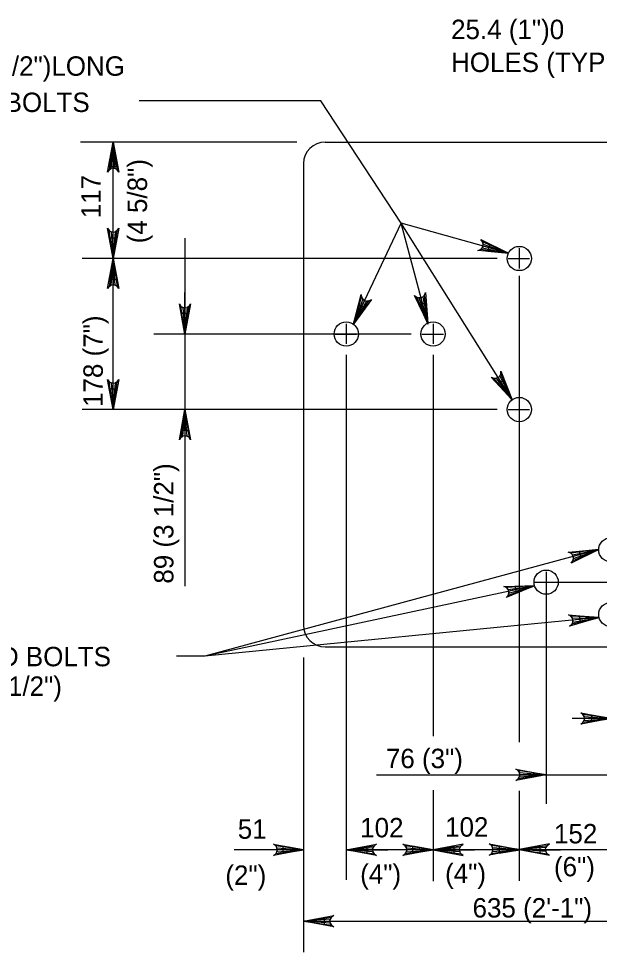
# Model space of a CAD drawing. Extents: x 0 to 36.3, y -66 to 0.
# Drawn here: x 13.18 to 16.77, y -15.09 to -9.32 of the extents above; entities that cross this region are included whole.
import ezdxf

# ---------------------------------------------------------------- set-up
doc = ezdxf.new("R2010")
doc.units = 0
doc.layers.add('2', color=7, linetype='Continuous')
doc.layers.add('3', color=7, linetype='Continuous')

msp = doc.modelspace()

# ---------------------------------------------------------------- linework, layer by layer
at = {"layer": '2'}
for p, q in [((15.0717, -10.0812), (18.1016, -10.0812)), ((14.9385, -10.2145), (14.9385, -13.0677)), ((16.2722, -10.7371), (16.2722, -10.862)), ((16.2028, -10.8009), (16.3361, -10.8009)), ((15.2025, -11.2038), (15.2025, -11.3287)), ((15.7394, -11.2038), (15.7394, -11.3287)), ((15.1331, -11.2677), (15.2663, -11.2677)), ((15.67, -11.2677), (15.8033, -11.2677)), ((16.2722, -11.6706), (16.2722, -11.7954)), ((16.2028, -11.7344), (16.3361, -11.7344)), ((16.4384, -12.7372), (16.4384, -12.862)), ((16.3691, -12.801), (16.5023, -12.801))]:
    msp.add_line(p, q, dxfattribs=at)
for centre in [(16.2722, -10.801), (15.2025, -11.2677), (15.7394, -11.2677), (16.2722, -11.7344), (16.8385, -12.601), (16.4385, -12.801), (16.8385, -13.001)]:
    msp.add_circle(centre, 0.075, dxfattribs=at)
for centre, start, end in [((15.0718, -10.2145), 90, 180), ((15.0718, -13.0677), 180, 270)]:
    msp.add_arc(centre, 0.1333, start, end, dxfattribs=at)
at = {"layer": '3'}
for p, q in [((15.0462, -9.8263), (13.9212, -9.8263)), ((15.543, -10.5827), (15.0462, -9.8263)), ((14.5169, -10.0812), (13.5602, -10.0812)), ((13.7607, -10.8009), (13.7607, -10.0812)), ((14.8968, -10.0812), (14.5169, -10.0812)), ((15.2467, -11.207), (15.543, -10.5827)), ((15.7061, -11.2005), (15.543, -10.5827)), ((16.2282, -11.6736), (15.543, -10.5827)), ((16.2048, -10.7682), (15.543, -10.5827)), ((14.2055, -10.6744), (14.2055, -12.8257)), ((14.4444, -10.8009), (13.5687, -10.8009)), ((13.7607, -11.7344), (13.7607, -10.8009)), ((16.1362, -10.8009), (14.4336, -10.8009)), ((16.2722, -10.9074), (16.2722, -13.789)), ((14.2055, -11.2677), (14.2055, -11.0116)), ((15.6033, -11.2677), (14.0134, -11.2677)), ((15.2025, -11.3954), (15.2025, -14.6398)), ((15.7394, -11.3954), (15.7394, -13.7531)), ((14.2707, -11.7344), (13.5687, -11.7344)), ((14.6835, -11.7344), (14.0134, -11.7344)), ((16.1362, -11.7344), (14.4336, -11.7344)), ((14.2055, -11.8624), (14.2055, -11.8277)), ((16.7634, -12.6002), (14.3277, -13.2589)), ((16.5009, -12.801), (18.7591, -12.801)), ((16.3668, -12.8232), (14.3277, -13.2589)), ((16.4384, -12.8635), (16.4384, -14.1707)), ((16.7658, -13.0195), (14.3277, -13.2589)), ((15.0717, -13.201), (18.1016, -13.201)), ((14.3277, -13.2589), (14.1525, -13.2589)), ((14.9385, -13.2664), (14.9385, -14.6467)), ((16.7184, -13.6429), (16.5984, -13.6429)), ((15.3898, -13.9908), (17.0763, -13.9908)), ((15.7394, -14.0854), (15.7394, -14.6492)), ((16.2722, -14.0899), (16.2722, -14.6467)), ((14.9385, -14.3606), (14.9385, -15.0885)), ((14.9385, -14.4546), (14.5105, -14.4546)), ((14.8104, -14.4546), (14.6823, -14.4546)), ((15.4833, -14.4546), (15.2349, -14.4546)), ((15.3306, -14.4546), (15.4587, -14.4546)), ((15.6114, -14.4546), (15.4833, -14.4546)), ((16.0203, -14.4546), (15.7718, -14.4546)), ((15.8675, -14.4546), (15.9956, -14.4546)), ((16.1483, -14.4546), (16.0203, -14.4546)), ((16.4003, -14.4546), (16.5283, -14.4546)), ((16.9437, -14.4546), (16.4003, -14.4546)), ((14.9385, -14.8964), (18.2348, -14.8964))]:
    msp.add_line(p, q, dxfattribs=at)
for points in [[(13.7607, -10.0812), (13.7957, -10.2676), (13.7858, -10.2532), (13.7732, -10.2458), (13.7607, -10.2437), (13.7482, -10.2458), (13.7357, -10.2532), (13.7258, -10.2676), (13.7607, -10.0812), (13.7357, -10.2532), (13.7482, -10.2458), (13.7607, -10.0812), (13.7607, -10.2437), (13.7732, -10.2458), (13.7607, -10.0812), (13.7858, -10.2532)], [(13.7607, -10.8009), (13.7258, -10.6145), (13.7357, -10.6288), (13.7482, -10.6363), (13.7607, -10.6384), (13.7732, -10.6363), (13.7858, -10.6288), (13.7957, -10.6145), (13.7607, -10.8009), (13.7858, -10.6288), (13.7732, -10.6363), (13.7607, -10.8009), (13.7607, -10.6384), (13.7482, -10.6363), (13.7607, -10.8009), (13.7357, -10.6288)], [(16.2048, -10.7682), (16.0158, -10.7515), (16.0323, -10.7458), (16.0428, -10.7357), (16.0482, -10.7243), (16.0496, -10.7118), (16.0458, -10.6977), (16.0347, -10.6843), (16.2048, -10.7682), (16.0458, -10.6977), (16.0496, -10.7118), (16.2048, -10.7682), (16.0482, -10.7243), (16.0428, -10.7357), (16.2048, -10.7682), (16.0323, -10.7458)], [(13.7607, -10.8009), (13.7957, -10.9873), (13.7858, -10.973), (13.7732, -10.9656), (13.7607, -10.9634), (13.7482, -10.9656), (13.7357, -10.973), (13.7258, -10.9873), (13.7607, -10.8009), (13.7357, -10.973), (13.7482, -10.9656), (13.7607, -10.8009), (13.7607, -10.9634), (13.7732, -10.9656), (13.7607, -10.8009), (13.7858, -10.973)], [(15.7061, -11.2005), (15.6247, -11.0292), (15.638, -11.0405), (15.652, -11.0445), (15.6646, -11.0434), (15.6762, -11.0381), (15.6863, -11.0277), (15.6923, -11.0113), (15.7061, -11.2005), (15.6863, -11.0277), (15.6762, -11.0381), (15.7061, -11.2005), (15.6646, -11.0434), (15.652, -11.0445), (15.7061, -11.2005), (15.638, -11.0405)], [(15.2467, -11.207), (15.295, -11.0236), (15.2978, -11.0408), (15.306, -11.0529), (15.3163, -11.0602), (15.3286, -11.0636), (15.343, -11.0623), (15.3582, -11.0536), (15.2467, -11.207), (15.343, -11.0623), (15.3286, -11.0636), (15.2467, -11.207), (15.3163, -11.0602), (15.306, -11.0529), (15.2467, -11.207), (15.2978, -11.0408)], [(14.2055, -11.2677), (14.1706, -11.0812), (14.1805, -11.0956), (14.193, -11.103), (14.2055, -11.1052), (14.218, -11.103), (14.2305, -11.0956), (14.2404, -11.0812), (14.2055, -11.2677), (14.2305, -11.0956), (14.218, -11.103), (14.2055, -11.2677), (14.2055, -11.1052), (14.193, -11.103), (14.2055, -11.2677), (14.1805, -11.0956)], [(16.2282, -11.6736), (16.0995, -11.5343), (16.1156, -11.5412), (16.1301, -11.5408), (16.1418, -11.536), (16.1513, -11.5275), (16.1579, -11.5146), (16.1587, -11.4972), (16.2282, -11.6736), (16.1579, -11.5146), (16.1513, -11.5275), (16.2282, -11.6736), (16.1418, -11.536), (16.1301, -11.5408), (16.2282, -11.6736), (16.1156, -11.5412)], [(13.7607, -11.7344), (13.7258, -11.548), (13.7357, -11.5623), (13.7482, -11.5697), (13.7607, -11.5719), (13.7732, -11.5697), (13.7858, -11.5623), (13.7957, -11.548), (13.7607, -11.7344), (13.7858, -11.5623), (13.7732, -11.5697), (13.7607, -11.7344), (13.7607, -11.5719), (13.7482, -11.5697), (13.7607, -11.7344), (13.7357, -11.5623)], [(14.2055, -11.7344), (14.2404, -11.9208), (14.2305, -11.9065), (14.218, -11.8991), (14.2055, -11.8969), (14.193, -11.8991), (14.1805, -11.9065), (14.1706, -11.9208), (14.2055, -11.7344), (14.1805, -11.9065), (14.193, -11.8991), (14.2055, -11.7344), (14.2055, -11.8969), (14.218, -11.8991), (14.2055, -11.7344), (14.2305, -11.9065)], [(16.7634, -12.6002), (16.5926, -12.6827), (16.6038, -12.6693), (16.6077, -12.6553), (16.6066, -12.6427), (16.6013, -12.6312), (16.5908, -12.621), (16.5743, -12.6152), (16.7634, -12.6002), (16.5908, -12.621), (16.6013, -12.6312), (16.7634, -12.6002), (16.6066, -12.6427), (16.6077, -12.6553), (16.7634, -12.6002), (16.6038, -12.6693)], [(16.3668, -12.8232), (16.1918, -12.8964), (16.2038, -12.8837), (16.2084, -12.8699), (16.2079, -12.8572), (16.2033, -12.8454), (16.1933, -12.8347), (16.1773, -12.828), (16.3668, -12.8232), (16.1933, -12.8347), (16.2033, -12.8454), (16.3668, -12.8232), (16.2079, -12.8572), (16.2084, -12.8699), (16.3668, -12.8232), (16.2038, -12.8837)], [(16.7658, -13.0195), (16.5837, -13.0725), (16.597, -13.0612), (16.6031, -13.048), (16.604, -13.0354), (16.6007, -13.0232), (16.5921, -13.0114), (16.5768, -13.0029), (16.7658, -13.0195), (16.5921, -13.0114), (16.6007, -13.0232), (16.7658, -13.0195), (16.604, -13.0354), (16.6031, -13.048), (16.7658, -13.0195), (16.597, -13.0612)], [(16.8384, -13.6429), (16.652, -13.6778), (16.6663, -13.6679), (16.6737, -13.6554), (16.6759, -13.6429), (16.6737, -13.6304), (16.6663, -13.6179), (16.652, -13.608), (16.8384, -13.6429), (16.6663, -13.6179), (16.6737, -13.6304), (16.8384, -13.6429), (16.6759, -13.6429), (16.6737, -13.6554), (16.8384, -13.6429), (16.6663, -13.6679)], [(16.4384, -13.9908), (16.252, -14.0257), (16.2663, -14.0157), (16.2737, -14.0032), (16.2759, -13.9908), (16.2737, -13.9782), (16.2663, -13.9657), (16.252, -13.9558), (16.4384, -13.9908), (16.2663, -13.9657), (16.2737, -13.9782), (16.4384, -13.9908), (16.2759, -13.9908), (16.2737, -14.0032), (16.4384, -13.9908), (16.2663, -14.0157)], [(14.9385, -14.4546), (14.7521, -14.4895), (14.7664, -14.4796), (14.7738, -14.4671), (14.776, -14.4546), (14.7738, -14.4421), (14.7664, -14.4296), (14.7521, -14.4197), (14.9385, -14.4546), (14.7664, -14.4296), (14.7738, -14.4421), (14.9385, -14.4546), (14.776, -14.4546), (14.7738, -14.4671), (14.9385, -14.4546), (14.7664, -14.4796)], [(15.2025, -14.4546), (15.3889, -14.4197), (15.3746, -14.4296), (15.3672, -14.4421), (15.365, -14.4546), (15.3672, -14.4671), (15.3746, -14.4796), (15.3889, -14.4895), (15.2025, -14.4546), (15.3746, -14.4796), (15.3672, -14.4671), (15.2025, -14.4546), (15.365, -14.4546), (15.3672, -14.4421), (15.2025, -14.4546), (15.3746, -14.4296)], [(15.7394, -14.4546), (15.553, -14.4895), (15.5673, -14.4796), (15.5747, -14.4671), (15.5769, -14.4546), (15.5747, -14.4421), (15.5673, -14.4296), (15.553, -14.4197), (15.7394, -14.4546), (15.5673, -14.4296), (15.5747, -14.4421), (15.7394, -14.4546), (15.5769, -14.4546), (15.5747, -14.4671), (15.7394, -14.4546), (15.5673, -14.4796)], [(15.7394, -14.4546), (15.9258, -14.4895), (15.9115, -14.4796), (15.9041, -14.4671), (15.9019, -14.4546), (15.9041, -14.4421), (15.9115, -14.4296), (15.9258, -14.4197), (15.7394, -14.4546), (15.9115, -14.4296), (15.9041, -14.4421), (15.7394, -14.4546), (15.9019, -14.4546), (15.9041, -14.4671), (15.7394, -14.4546), (15.9115, -14.4796)], [(16.2722, -14.4539), (16.0858, -14.4888), (16.1002, -14.4789), (16.1076, -14.4664), (16.1097, -14.4539), (16.1076, -14.4414), (16.1002, -14.4289), (16.0858, -14.4189), (16.2722, -14.4539), (16.1002, -14.4289), (16.1076, -14.4414), (16.2722, -14.4539), (16.1097, -14.4539), (16.1076, -14.4664), (16.2722, -14.4539), (16.1002, -14.4789)], [(16.2722, -14.4539), (16.4587, -14.4888), (16.4443, -14.4789), (16.4369, -14.4664), (16.4348, -14.4539), (16.4369, -14.4414), (16.4443, -14.4289), (16.4587, -14.4189), (16.2722, -14.4539), (16.4443, -14.4289), (16.4369, -14.4414), (16.2722, -14.4539), (16.4348, -14.4539), (16.4369, -14.4664), (16.2722, -14.4539), (16.4443, -14.4789)], [(14.9385, -14.8964), (15.1249, -14.8615), (15.1106, -14.8714), (15.1032, -14.8839), (15.101, -14.8964), (15.1032, -14.9089), (15.1106, -14.9214), (15.1249, -14.9313), (14.9385, -14.8964), (15.1106, -14.9214), (15.1032, -14.9089), (14.9385, -14.8964), (15.101, -14.8964), (15.1032, -14.8839), (14.9385, -14.8964), (15.1106, -14.8714)]]:
    msp.add_lwpolyline(points, dxfattribs=at)
for points in [[(13.7394, -10.2326), (13.7821, -10.2326), (13.7607, -10.1046)], [(13.7394, -10.6729), (13.7821, -10.6729), (13.7607, -10.8009)], [(16.0888, -10.7136), (16.0773, -10.7547), (16.2064, -10.7683)], [(13.7394, -10.929), (13.7821, -10.929), (13.7607, -10.8009)], [(15.6956, -11.0771), (15.6543, -11.088), (15.7077, -11.2063)], [(15.3187, -11.1051), (15.2802, -11.0868), (15.2442, -11.2115)], [(14.1842, -11.1396), (14.2268, -11.1396), (14.2055, -11.2677)], [(16.1777, -11.553), (16.1417, -11.5757), (16.228, -11.6727)], [(13.7394, -11.6063), (13.7821, -11.6063), (13.7607, -11.7344)], [(14.1842, -11.8624), (14.2268, -11.8624), (14.2055, -11.7344)], [(16.6423, -12.6122), (16.6528, -12.6508), (16.7634, -12.6002)], [(16.2452, -12.8287), (16.2537, -12.8678), (16.3668, -12.8232)], [(16.6444, -13.0114), (16.6483, -13.0512), (16.7658, -13.0196)], [(16.7184, -13.6229), (16.7184, -13.6629), (16.8384, -13.6429)], [(14.8104, -14.4332), (14.8104, -14.4759), (14.9385, -14.4546)], [(15.3306, -14.4332), (15.3306, -14.4759), (15.2025, -14.4546)], [(15.6114, -14.4332), (15.6114, -14.4759), (15.7394, -14.4546)], [(15.8675, -14.4332), (15.8675, -14.4759), (15.7394, -14.4546)], [(16.1483, -14.4332), (16.1483, -14.4759), (16.2763, -14.4546)], [(16.4003, -14.4332), (16.4003, -14.4759), (16.2722, -14.4546)], [(15.0666, -14.8751), (15.0666, -14.9177), (14.9385, -14.8964)]]:
    msp.add_lwpolyline(points, close=True, dxfattribs=at)

# ---------------------------------------------------------------- texts
for s, p in [('25.4 (1")0', (15.8508, -9.4453)), ('25.4 (1")0 x 38 (1 1/2")LONG', (11.7669, -9.6717)), ('HOLES (TYP.)', (15.8508, -9.6487)), ('STUD MOUNTED BOLTS', (11.7531, -9.8957)), ('STUD MOUNTED BOLTS', (11.8845, -13.3208)), ('25.4(1")0 x 38 (1 1/2")', (11.8767, -13.5036)), ('76 (3")', (15.4478, -13.9504)), ('51', (14.532, -14.3867)), ('102', (15.2887, -14.3781)), ('102', (15.8137, -14.3737)), ('152', (16.4871, -14.4153)), ('(4")', (15.2887, -14.6647)), ('(4")', (15.8137, -14.6603)), ('(6")', (16.4871, -14.6187)), ('(2")', (14.455, -14.6717)), ('635 (2\'-1")', (15.9836, -14.8734))]:
    msp.add_text(s, height=0.12, dxfattribs=at).set_placement(p)
for s, p in [('(4 5/8")', (13.9705, -10.7071)), ('117', (13.6838, -10.5522)), ('178 (7")', (13.6974, -11.7184)), ('89 (3 1/2")', (14.1339, -12.8104))]:
    msp.add_text(s, height=0.12, rotation=90, dxfattribs=at).set_placement(p)

doc.saveas('drawing.dxf')
